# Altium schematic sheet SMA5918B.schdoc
size 127 x 101 mm
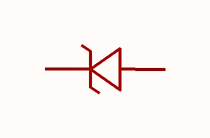
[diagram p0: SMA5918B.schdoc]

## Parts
D?  sma5918b  [SMAG_L4.3-W2.6-LS5.3-RD]  (value not drawn)

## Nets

Not connected (* = marked no-connect by the designer): D? 1(C) 2(A)

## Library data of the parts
D? = sma5918b: 二极管配置:1个独立式;稳压值(标称值):5.1V;稳压值(范围):-;耗散功率(Pd):3W;; Manufacturer: CJ(江苏长电/长晶); AddInBom: yes; ModelId: 3cd8680d946b497db8ea5837610a9736; ModelTransform: 208.661,102.362,0,0,0,0,0,0,0; Diode Configuration: 1个独立式; Zener Voltage(Nom): 5.1V; Reverse Leakage Current (Ir): 5uA; Pd - Power Dissipation: 3W; Impedance(Zzt): 3.5Ω; Impedance(Zzk): 550Ω; Operating Junction Temperature Range: -55℃~+150℃; Tolerance: ±5%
